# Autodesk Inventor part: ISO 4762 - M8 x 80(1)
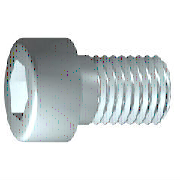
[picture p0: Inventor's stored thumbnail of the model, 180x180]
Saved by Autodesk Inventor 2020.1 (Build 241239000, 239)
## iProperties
Created: 2019-01
Part Number: ISO 4762 - M8 x 80(1)
Material: Edelstahl, 440C
Description: Innensechskantschraube
Document SubType Name: Modeling
Standard: ISO 4762
Designer: lutzd
Standard Revision: Fourth edition 2004-03-01
Standards Organization: ISO
Language: de-DE
Size Designation: M8 x 80
Categories: <MemberInstance><Categories><Category DisplayName="Verbindungselemente" InternalName="e4da775c-781d-43d5-af7c-5136215cf5a6" Mnemonic="FSTN"><Category DisplayNam
Mass: 38.1426 g
Surface Area: 26.6699 cm^2
Volume: 4.92163 cm^3
Density: 7.75 g/cm^3
Appearance: Halbpoliert
IsCustomPart: 0
Author: lutzd
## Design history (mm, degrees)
workplane "Work Plane1"
fillet "Fillet2" dims "d30" = 0.1 (= R)
sketch "Skizze1"
  geometry: L1 (-2, 0)-(80, 0); L2 (80, 0)-(80, 4); L3 (80, 4)-(52, 4); L4 (52, 4)-(51.233, 4); L5 (51.233, 4)-(0, 4); L6 (0, 4)-(0, 6.5); L7 (0, 6.5)-(-8, 6.5); L8 (-8, 6.5)-(-8, 3.464); L9 (-8, 3.464)-(-4, 3.464); L10 (-4, 3.464)-(-2, 0); L11 (-25.6, 0)-(97.6, 0) reference; L12 (0, -1.3)-(0, 7.8) reference; L13 (52, 4)-(0, 4)
  constraints: 22 end point, 6 parallel, 2 collinear, 2 perpendicular, 1 horizontal, 1 point on line
  dimensions: "d1" = 28 distance from line of L3.end L2 (= GEL); "d2" = 0.76691 distance of L4.end L3.end (computed from GAL); "d3" = 8 distance between parallel lines of L8 L6 (= KOH); "d4" = 4 distance of L8.end L9.end (= INTI); "d5" = 60 deg angle of L10 L1; "d6" = 8 diameter of L3 L1 (= GD); "d7" = 8 diameter of L5 L1 (= BDM); "d8" = 6.9282 diameter of L9 L1 (= 1.1547 x SW); "d9" = 13 diameter of L7 L1 (= KOD); "d26" = 80 distance between parallel lines of L12 L2 (= NLG)
revolve "Körper" sketch "Skizze1" stored, may be unused: angle "d10" = 90 deg
sketch "Skizze2"
  geometry: L1 (0, -9.1)-(0, 9.1) reference; L2 (-9.1, 0)-(9.1, 0) reference; L3 (3.464, 0)-(1.732, -3); L4 (1.732, -3)-(-1.732, -3); L5 (-1.732, -3)-(-3.464, 0); L6 (-3.464, 0)-(-1.732, 3); L7 (-1.732, 3)-(1.732, 3); L8 (1.732, 3)-(3.464, 0); 2 further points
  constraints: 12 end point, 1 coincident, 1 horizontal alignment, 1 point on line, 12 other
extrude "Loch" join sketch "Skizze2" stored distance "d11" = 10; taper "d12" = 0 deg
body "Solid1"
fillet "Rundung1" dims "d17" = 0.8 (= RR)
feature "Gewinde" dims "d13" = 28 (= GEL), "d14" = 0
chamfer "Fase1" distance "d15" = 0.76681 (= -0.5 x SPD + 0.5 x GD); stored, may be unused: second distance "d16" = 0.76681 (= GUL), angle "d27" = 45 deg
other parameters: "GD" = 8 [user parameter; used in 2 equation terms], "NLG" = 80 [user parameter; used in 1 equation term], "GEL" = 28 [user parameter; used in 2 equation terms], "KOD" = 13 [user parameter; used in 1 equation term], "KOH" = 8 [user parameter; used in 1 equation term], "INTI" = 4 [user parameter; used in 1 equation term], "GAL" = 0.76681 (= 0.61345 x PTC) [user parameter; used in 1 equation term], "GUL" = 0.76681 (= 0.61345 x PTC) [user parameter; used in 1 equation term], "BDM" = 8 (= NND) [user parameter; used in 1 equation term], "SW" = 6 [user parameter; used in 2 equation terms], "RR" = 0.8 [user parameter; used in 1 equation term], "SPD" = 6.46637 (= NND - 1.2269 x PTC) [user parameter; used in 1 equation term], "d19" = 0, "d28" = 0, "d29" = 0, "R" = 0.1 [user parameter; used in 1 equation term], "TOA" = 30 deg [user parameter], "GD1" = 6.46637 (= THREADDIA - 1.2269 x PTC) [user parameter], "THREADDIA" = 8 [user parameter; used in 1 equation term], "FAWI" = 45 deg [user parameter], "TPU" = 8 (computed from PTC) [user parameter], "PTC" = 1.25 [user parameter; used in 5 equation terms], "NND" = 8 [user parameter; used in 2 equation terms], "E0" = 6.93 (= 1.155 x SW) [user parameter]
